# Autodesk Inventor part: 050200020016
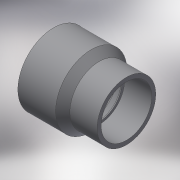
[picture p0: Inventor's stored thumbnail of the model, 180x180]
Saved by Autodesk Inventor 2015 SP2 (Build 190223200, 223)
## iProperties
Created: 2017-10
Part Number: 050200020016
Material: Generic
Description: PLASSON REDUCING SOCKET M.F.20(16)16 CEMENTED
Document SubType Name: Modeling
Designer: KIM
Density: 1 g/cm^3
Appearance: Default
Author: KIM
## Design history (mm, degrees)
derived "050200.ipt"
feature "Solid1::050200.ipt"
tag "TaggingFeature1"
body "Solid1"
other parameters: "d0" = 36, "d1" = 16, "d2" = 14, "d3" = 14, "d4" = 16, "d6" = 16, "d8" = 14.4, "d9" = 45 deg, "d12" = 0.16, "d_" = 16, "d_1" = 16, "L_" = 16, "l_" = 14, "l_1" = 14, "H_" = 36, "d11" = 0
